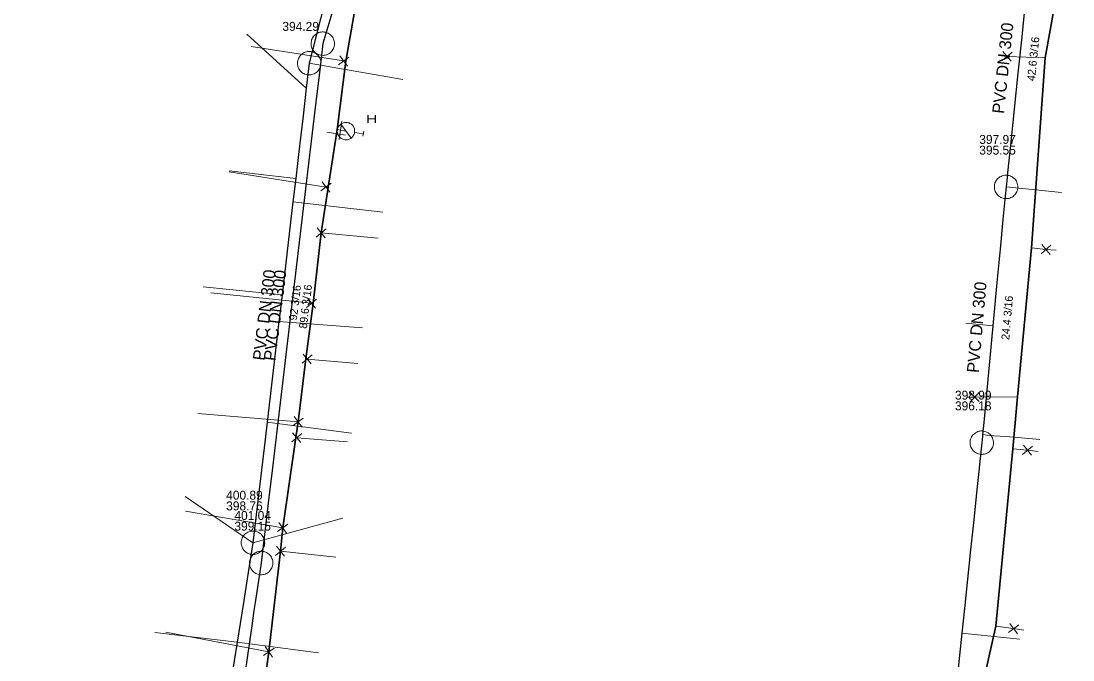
# Model space of a CAD drawing. Extents: x -772952 to -772403, y -1033777 to -1033210.
# Drawn here: x -772837.8 to -772731.9, y -1033431 to -1033366.6 of the extents above; entities that cross this region are included whole.
import ezdxf

# ---------------------------------------------------------------- set-up
doc = ezdxf.new("R2010")
doc.units = 0
doc.header["$LTSCALE"] = 0.36
for name, color, linetype, lineweight in [('15', 7, 'Continuous', 13), ('16', 7, 'Continuous', 35), ('2', 7, 'Continuous', 25), ('20', 7, 'Continuous', 13), ('4', 7, 'Continuous', 13), ('57', 7, 'Continuous', 13), ('59', 7, 'Continuous', 13)]:
    doc.layers.add(name, color=color, linetype=linetype, lineweight=lineweight)
doc.layers.add('3', color=7, linetype='Continuous')
doc.layers.add('6', color=7, linetype='Continuous')

msp = doc.modelspace()

# ---------------------------------------------------------------- linework, layer by layer
at = {"layer": '15'}
for p, q in [((-772738.012, -1033369.776), (-772739.011, -1033370.611)), ((-772738.098, -1033370.687), (-772738.924, -1033369.695)), ((-772804.771, -1033370.263), (-772805.823, -1033371.03)), ((-772804.917, -1033371.166), (-772805.674, -1033370.122)), ((-772805.749, -1033378.554), (-772805.472, -1033376.712)), ((-772805.101, -1033378.119), (-772806.941, -1033377.836)), ((-772806.536, -1033382.968), (-772807.59, -1033383.732)), ((-772806.684, -1033383.871), (-772807.439, -1033382.825)), ((-772808.058, -1033388.377), (-772807.055, -1033387.548)), ((-772807.967, -1033387.467), (-772807.147, -1033388.463)), ((-772735.097, -1033390.054), (-772734.106, -1033389.209)), ((-772735.02, -1033389.142), (-772734.185, -1033390.126)), ((-772808.022, -1033394.638), (-772809.031, -1033395.459)), ((-772808.12, -1033395.547), (-772808.932, -1033394.545)), ((-772809.46, -1033401.071), (-772808.46, -1033400.238)), ((-772809.373, -1033400.16), (-772808.549, -1033401.154)), ((-772741.317, -1033404.029), (-772742.234, -1033404.954)), ((-772741.318, -1033404.944), (-772742.232, -1033404.034)), ((-772810.387, -1033407.365), (-772809.351, -1033406.597)), ((-772809.483, -1033407.502), (-772810.26, -1033406.458)), ((-772810.511, -1033408.996), (-772809.516, -1033408.157)), ((-772810.429, -1033408.085), (-772809.599, -1033409.073)), ((-772736.971, -1033410.255), (-772735.962, -1033409.433)), ((-772736.874, -1033409.345), (-772736.061, -1033410.347)), ((-772810.899, -1033417.277), (-772811.961, -1033418.03)), ((-772811.057, -1033418.178), (-772811.801, -1033417.124)), ((-772812.042, -1033419.512), (-772811.232, -1033420.516)), ((-772812.142, -1033420.421), (-772811.131, -1033419.602)), ((-772738.375, -1033428.185), (-772737.336, -1033427.401)), ((-772738.244, -1033427.279), (-772737.469, -1033428.311)), ((-772812.276, -1033429.761), (-772813.353, -1033430.492)), ((-772812.453, -1033430.659), (-772813.175, -1033429.589))]:
    msp.add_line(p, q, dxfattribs=at)
at = {"layer": '16'}
for points in [[(-772806.021, -1033377.978), (-772805.954, -1033377.548), (-772805.072, -1033370.662), (-772803.861, -1033363.758), (-772800.241, -1033353.386), (-772792.475, -1033337.699)], [(-772752.004, -1033530.359), (-772751.19, -1033518.811), (-772750.826, -1033515.51), (-772749.541, -1033501.15), (-772748.782, -1033492.67), (-772747.697, -1033482.83), (-772745.37, -1033461.714), (-772744.103, -1033448.559), (-772744.068, -1033448.195), (-772743.857, -1033446.285), (-772742.735, -1033441.315), (-772739.627, -1033427.552), (-772737.918, -1033409.688), (-772737.464, -1033404.467), (-772736.037, -1033389.46), (-772734.688, -1033370.337), (-772732.3, -1033357.109), (-772731.88, -1033345.97)], [(-772837.765, -1033512.662), (-772833.548, -1033502.146), (-772829.238, -1033493.795), (-772826.857, -1033488.289), (-772826.66, -1033487.846), (-772820.068, -1033470.473), (-772819.886, -1033469.795), (-772816.921, -1033457.655), (-772813.552, -1033435.519), (-772813.35, -1033434.04), (-772813.183, -1033432.822), (-772812.813, -1033430.125), (-772811.638, -1033420.013), (-772811.429, -1033417.653), (-772810.102, -1033408.565), (-772809.872, -1033406.991), (-772809.089, -1033400.644), (-772808.375, -1033395.068), (-772807.557, -1033387.964), (-772806.853, -1033383.381), (-772806.021, -1033377.978)]]:
    msp.add_lwpolyline(points, dxfattribs=at)
at = {"layer": '2'}
for points in [[(-772735.86, -1033356.94), (-772735.964, -1033357.942), (-772736.014, -1033358.425), (-772736.295, -1033361.116), (-772736.676, -1033364.769), (-772737.037, -1033368.227), (-772737.417, -1033371.875), (-772737.796, -1033375.512), (-772738.174, -1033379.131), (-772738.465, -1033381.925), (-772738.512, -1033382.371), (-772738.612, -1033383.334)], [(-772804.68, -1033359.76), (-772805.372, -1033362.098), (-772805.996, -1033364.204), (-772806.588, -1033366.202), (-772807.39, -1033368.91)], [(-772806.72, -1033362.82), (-772807.267, -1033364.982), (-772808.76, -1033370.88)], [(-772807.39, -1033368.91), (-772807.739, -1033371.853), (-772807.957, -1033373.694), (-772808.221, -1033375.921), (-772809.191, -1033384.102), (-772810.296, -1033393.415), (-772811.17, -1033400.791), (-772812.452, -1033411.601), (-772812.81, -1033414.614), (-772813.59, -1033421.19)], [(-772808.76, -1033370.88), (-772809.054, -1033373.394), (-772809.382, -1033376.191), (-772809.838, -1033380.074), (-772810.121, -1033382.493), (-772810.396, -1033384.832), (-772811.495, -1033394.212), (-772811.721, -1033396.139), (-772811.808, -1033396.879), (-772812.998, -1033407.026), (-772813.298, -1033409.587), (-772814.42, -1033419.15)], [(-772738.612, -1033383.334), (-772738.7, -1033384.261), (-772738.924, -1033386.621), (-772739.207, -1033389.594), (-772739.528, -1033392.97), (-772739.941, -1033397.312), (-772740.866, -1033407.047), (-772740.977, -1033408.213), (-772740.998, -1033408.434), (-772741.06, -1033409.08)], [(-772741.06, -1033409.08), (-772741.253, -1033410.929), (-772741.326, -1033411.63), (-772741.587, -1033414.12), (-772741.871, -1033416.843), (-772742.189, -1033419.878), (-772742.495, -1033422.808), (-772742.806, -1033425.788), (-772743.066, -1033428.271), (-772743.3, -1033430.508), (-772744.701, -1033443.912), (-772744.889, -1033445.705), (-772745.203, -1033448.714), (-772745.553, -1033452.058), (-772745.859, -1033454.983), (-772746.171, -1033457.964), (-772746.344, -1033459.622), (-772746.477, -1033460.894), (-772746.527, -1033461.369), (-772746.66, -1033462.606)], [(-772814.42, -1033419.15), (-772814.998, -1033422.779), (-772815.417, -1033425.405), (-772816.014, -1033429.153), (-772817.813, -1033440.441), (-772819.293, -1033449.728), (-772820.068, -1033454.588), (-772820.4, -1033456.67)], [(-772813.59, -1033421.19), (-772813.756, -1033422.304), (-772813.954, -1033423.632), (-772814.184, -1033425.18), (-772814.339, -1033425.976), (-772814.533, -1033427.52), (-772815.252, -1033432.346), (-772815.998, -1033437.348), (-772816.86, -1033443.13), (-772817.761, -1033449.175), (-772818.006, -1033450.823), (-772818.251, -1033452.464), (-772818.488, -1033454.051), (-772818.61, -1033454.87)]]:
    msp.add_lwpolyline(points, dxfattribs=at)
at = {"layer": '20'}
for p, q in [((-772804.537, -1033378.415), (-772805.578, -1033377.007)), ((-772804.181, -1033377.842), (-772803.307, -1033377.973)), ((-772803.267, -1033377.706), (-772803.347, -1033378.241))]:
    msp.add_line(p, q, dxfattribs=at)
msp.add_lwpolyline([(-772805.187, -1033378.581), (-772805.097, -1033378.59), (-772805.006, -1033378.59), (-772804.913, -1033378.579), (-772804.826, -1033378.56), (-772804.738, -1033378.531), (-772804.654, -1033378.493), (-772804.576, -1033378.446), (-772804.501, -1033378.393), (-772804.435, -1033378.33), (-772804.374, -1033378.262), (-772804.321, -1033378.187), (-772804.274, -1033378.107), (-772804.238, -1033378.024), (-772804.21, -1033377.937), (-772804.193, -1033377.846), (-772804.183, -1033377.755), (-772804.183, -1033377.664), (-772804.194, -1033377.573), (-772804.215, -1033377.483), (-772804.244, -1033377.396), (-772804.283, -1033377.313), (-772804.327, -1033377.234), (-772804.383, -1033377.16), (-772804.444, -1033377.093), (-772804.513, -1033377.032), (-772804.588, -1033376.978), (-772804.667, -1033376.934), (-772804.752, -1033376.897), (-772804.839, -1033376.87), (-772804.929, -1033376.85), (-772805.019, -1033376.843), (-772805.11, -1033376.843), (-772805.203, -1033376.853), (-772805.29, -1033376.873), (-772805.378, -1033376.902), (-772805.462, -1033376.94), (-772805.54, -1033376.987), (-772805.615, -1033377.04), (-772805.681, -1033377.103), (-772805.742, -1033377.171), (-772805.795, -1033377.246), (-772805.842, -1033377.326), (-772805.877, -1033377.41), (-772805.906, -1033377.496), (-772805.923, -1033377.587), (-772805.933, -1033377.678), (-772805.931, -1033377.77), (-772805.922, -1033377.86), (-772805.901, -1033377.95), (-772805.872, -1033378.037), (-772805.833, -1033378.12), (-772805.789, -1033378.199), (-772805.733, -1033378.272), (-772805.672, -1033378.34), (-772805.603, -1033378.401), (-772805.528, -1033378.455), (-772805.449, -1033378.499), (-772805.364, -1033378.536), (-772805.277, -1033378.563), (-772805.189, -1033378.581)], dxfattribs=at)
at = {"layer": '4'}
for points in [[(-772806.21, -1033368.91), (-772806.216, -1033368.791), (-772806.234, -1033368.674), (-772806.263, -1033368.558), (-772806.304, -1033368.447), (-772806.356, -1033368.34), (-772806.419, -1033368.239), (-772806.492, -1033368.144), (-772806.573, -1033368.058), (-772806.663, -1033367.98), (-772806.761, -1033367.911), (-772806.864, -1033367.853), (-772806.973, -1033367.806), (-772807.087, -1033367.769), (-772807.203, -1033367.744), (-772807.321, -1033367.732), (-772807.44, -1033367.731), (-772807.559, -1033367.742), (-772807.675, -1033367.765), (-772807.789, -1033367.799), (-772807.899, -1033367.845), (-772808.004, -1033367.902), (-772808.102, -1033367.969), (-772808.193, -1033368.045), (-772808.276, -1033368.13), (-772808.35, -1033368.224), (-772808.414, -1033368.324), (-772808.468, -1033368.43), (-772808.511, -1033368.541), (-772808.543, -1033368.655), (-772808.562, -1033368.773), (-772808.57, -1033368.892), (-772808.566, -1033369.01), (-772808.55, -1033369.128), (-772808.522, -1033369.244), (-772808.483, -1033369.356), (-772808.432, -1033369.464), (-772808.371, -1033369.566), (-772808.3, -1033369.662), (-772808.22, -1033369.749), (-772808.131, -1033369.829), (-772808.035, -1033369.899), (-772807.932, -1033369.959), (-772807.824, -1033370.008), (-772807.711, -1033370.046), (-772807.595, -1033370.072), (-772807.477, -1033370.087), (-772807.358, -1033370.09), (-772807.24, -1033370.081), (-772807.122, -1033370.06), (-772807.008, -1033370.027), (-772806.898, -1033369.983), (-772806.792, -1033369.928), (-772806.693, -1033369.862), (-772806.6, -1033369.787), (-772806.516, -1033369.703), (-772806.441, -1033369.611), (-772806.375, -1033369.512), (-772806.319, -1033369.407), (-772806.275, -1033369.297), (-772806.241, -1033369.183), (-772806.22, -1033369.066), (-772806.21, -1033368.947)], [(-772807.58, -1033370.88), (-772807.586, -1033370.761), (-772807.604, -1033370.644), (-772807.633, -1033370.528), (-772807.674, -1033370.417), (-772807.726, -1033370.31), (-772807.789, -1033370.209), (-772807.862, -1033370.114), (-772807.943, -1033370.028), (-772808.033, -1033369.95), (-772808.131, -1033369.881), (-772808.234, -1033369.823), (-772808.343, -1033369.776), (-772808.457, -1033369.739), (-772808.573, -1033369.714), (-772808.691, -1033369.702), (-772808.81, -1033369.701), (-772808.929, -1033369.712), (-772809.045, -1033369.735), (-772809.159, -1033369.769), (-772809.269, -1033369.815), (-772809.374, -1033369.872), (-772809.472, -1033369.939), (-772809.563, -1033370.015), (-772809.646, -1033370.1), (-772809.72, -1033370.194), (-772809.784, -1033370.294), (-772809.838, -1033370.4), (-772809.881, -1033370.511), (-772809.913, -1033370.625), (-772809.932, -1033370.743), (-772809.94, -1033370.862), (-772809.936, -1033370.98), (-772809.92, -1033371.098), (-772809.892, -1033371.214), (-772809.853, -1033371.326), (-772809.802, -1033371.434), (-772809.741, -1033371.536), (-772809.67, -1033371.632), (-772809.59, -1033371.719), (-772809.501, -1033371.799), (-772809.405, -1033371.869), (-772809.302, -1033371.929), (-772809.194, -1033371.978), (-772809.081, -1033372.016), (-772808.965, -1033372.042), (-772808.847, -1033372.057), (-772808.728, -1033372.06), (-772808.61, -1033372.051), (-772808.492, -1033372.03), (-772808.378, -1033371.997), (-772808.268, -1033371.953), (-772808.162, -1033371.898), (-772808.063, -1033371.832), (-772807.97, -1033371.757), (-772807.886, -1033371.673), (-772807.811, -1033371.581), (-772807.745, -1033371.482), (-772807.689, -1033371.377), (-772807.645, -1033371.267), (-772807.611, -1033371.153), (-772807.59, -1033371.036), (-772807.58, -1033370.917)], [(-772737.431, -1033383.334), (-772737.438, -1033383.215), (-772737.456, -1033383.098), (-772737.485, -1033382.982), (-772737.526, -1033382.871), (-772737.578, -1033382.764), (-772737.641, -1033382.663), (-772737.713, -1033382.568), (-772737.794, -1033382.482), (-772737.885, -1033382.404), (-772737.983, -1033382.335), (-772738.086, -1033382.277), (-772738.195, -1033382.23), (-772738.309, -1033382.193), (-772738.424, -1033382.168), (-772738.543, -1033382.156), (-772738.662, -1033382.155), (-772738.781, -1033382.166), (-772738.897, -1033382.189), (-772739.011, -1033382.223), (-772739.12, -1033382.269), (-772739.225, -1033382.326), (-772739.324, -1033382.393), (-772739.414, -1033382.469), (-772739.498, -1033382.554), (-772739.571, -1033382.648), (-772739.636, -1033382.748), (-772739.69, -1033382.854), (-772739.733, -1033382.965), (-772739.765, -1033383.079), (-772739.784, -1033383.197), (-772739.792, -1033383.316), (-772739.788, -1033383.434), (-772739.772, -1033383.552), (-772739.744, -1033383.668), (-772739.705, -1033383.78), (-772739.654, -1033383.888), (-772739.593, -1033383.99), (-772739.522, -1033384.086), (-772739.441, -1033384.173), (-772739.353, -1033384.253), (-772739.257, -1033384.323), (-772739.154, -1033384.383), (-772739.046, -1033384.432), (-772738.933, -1033384.47), (-772738.816, -1033384.496), (-772738.699, -1033384.511), (-772738.58, -1033384.514), (-772738.462, -1033384.505), (-772738.343, -1033384.484), (-772738.23, -1033384.451), (-772738.12, -1033384.407), (-772738.014, -1033384.352), (-772737.914, -1033384.286), (-772737.821, -1033384.211), (-772737.738, -1033384.127), (-772737.663, -1033384.035), (-772737.597, -1033383.936), (-772737.541, -1033383.831), (-772737.497, -1033383.721), (-772737.463, -1033383.607), (-772737.441, -1033383.49), (-772737.431, -1033383.371)], [(-772739.88, -1033409.08), (-772739.886, -1033408.961), (-772739.904, -1033408.844), (-772739.933, -1033408.728), (-772739.974, -1033408.617), (-772740.026, -1033408.51), (-772740.089, -1033408.409), (-772740.162, -1033408.314), (-772740.243, -1033408.228), (-772740.333, -1033408.15), (-772740.431, -1033408.081), (-772740.534, -1033408.023), (-772740.643, -1033407.976), (-772740.757, -1033407.939), (-772740.873, -1033407.914), (-772740.991, -1033407.902), (-772741.11, -1033407.901), (-772741.229, -1033407.912), (-772741.345, -1033407.935), (-772741.459, -1033407.969), (-772741.569, -1033408.015), (-772741.674, -1033408.072), (-772741.772, -1033408.139), (-772741.863, -1033408.215), (-772741.946, -1033408.3), (-772742.02, -1033408.394), (-772742.084, -1033408.494), (-772742.138, -1033408.6), (-772742.181, -1033408.711), (-772742.213, -1033408.825), (-772742.232, -1033408.943), (-772742.24, -1033409.062), (-772742.236, -1033409.18), (-772742.22, -1033409.298), (-772742.192, -1033409.414), (-772742.153, -1033409.526), (-772742.102, -1033409.634), (-772742.041, -1033409.736), (-772741.97, -1033409.832), (-772741.89, -1033409.919), (-772741.801, -1033409.999), (-772741.705, -1033410.069), (-772741.602, -1033410.129), (-772741.494, -1033410.178), (-772741.381, -1033410.216), (-772741.265, -1033410.242), (-772741.147, -1033410.257), (-772741.028, -1033410.26), (-772740.91, -1033410.251), (-772740.792, -1033410.23), (-772740.678, -1033410.197), (-772740.568, -1033410.153), (-772740.462, -1033410.098), (-772740.363, -1033410.032), (-772740.27, -1033409.957), (-772740.186, -1033409.873), (-772740.111, -1033409.781), (-772740.045, -1033409.682), (-772739.989, -1033409.577), (-772739.945, -1033409.467), (-772739.911, -1033409.353), (-772739.89, -1033409.236), (-772739.88, -1033409.117)], [(-772813.24, -1033419.15), (-772813.246, -1033419.031), (-772813.264, -1033418.914), (-772813.293, -1033418.798), (-772813.334, -1033418.687), (-772813.386, -1033418.58), (-772813.449, -1033418.479), (-772813.522, -1033418.384), (-772813.603, -1033418.298), (-772813.693, -1033418.22), (-772813.791, -1033418.151), (-772813.894, -1033418.093), (-772814.003, -1033418.046), (-772814.117, -1033418.009), (-772814.233, -1033417.984), (-772814.351, -1033417.972), (-772814.47, -1033417.971), (-772814.589, -1033417.982), (-772814.705, -1033418.005), (-772814.819, -1033418.039), (-772814.929, -1033418.085), (-772815.034, -1033418.142), (-772815.132, -1033418.209), (-772815.223, -1033418.285), (-772815.306, -1033418.37), (-772815.38, -1033418.464), (-772815.444, -1033418.564), (-772815.498, -1033418.67), (-772815.541, -1033418.781), (-772815.573, -1033418.895), (-772815.592, -1033419.013), (-772815.6, -1033419.132), (-772815.596, -1033419.25), (-772815.58, -1033419.368), (-772815.552, -1033419.484), (-772815.513, -1033419.596), (-772815.462, -1033419.704), (-772815.401, -1033419.806), (-772815.33, -1033419.902), (-772815.25, -1033419.989), (-772815.161, -1033420.069), (-772815.065, -1033420.139), (-772814.962, -1033420.199), (-772814.854, -1033420.248), (-772814.741, -1033420.286), (-772814.625, -1033420.312), (-772814.507, -1033420.327), (-772814.388, -1033420.33), (-772814.27, -1033420.321), (-772814.152, -1033420.3), (-772814.038, -1033420.267), (-772813.928, -1033420.223), (-772813.822, -1033420.168), (-772813.723, -1033420.102), (-772813.63, -1033420.027), (-772813.546, -1033419.943), (-772813.471, -1033419.851), (-772813.405, -1033419.752), (-772813.349, -1033419.647), (-772813.305, -1033419.537), (-772813.271, -1033419.423), (-772813.25, -1033419.306), (-772813.24, -1033419.187)], [(-772812.409, -1033421.19), (-772812.416, -1033421.071), (-772812.434, -1033420.954), (-772812.463, -1033420.838), (-772812.504, -1033420.727), (-772812.556, -1033420.62), (-772812.619, -1033420.519), (-772812.691, -1033420.424), (-772812.772, -1033420.338), (-772812.863, -1033420.26), (-772812.961, -1033420.191), (-772813.064, -1033420.133), (-772813.173, -1033420.086), (-772813.287, -1033420.049), (-772813.402, -1033420.024), (-772813.521, -1033420.012), (-772813.64, -1033420.011), (-772813.759, -1033420.022), (-772813.875, -1033420.045), (-772813.989, -1033420.079), (-772814.098, -1033420.125), (-772814.203, -1033420.182), (-772814.302, -1033420.249), (-772814.392, -1033420.325), (-772814.476, -1033420.41), (-772814.549, -1033420.504), (-772814.614, -1033420.604), (-772814.668, -1033420.71), (-772814.711, -1033420.821), (-772814.743, -1033420.935), (-772814.762, -1033421.053), (-772814.77, -1033421.172), (-772814.766, -1033421.29), (-772814.75, -1033421.408), (-772814.722, -1033421.524), (-772814.683, -1033421.636), (-772814.632, -1033421.744), (-772814.571, -1033421.846), (-772814.5, -1033421.942), (-772814.419, -1033422.029), (-772814.331, -1033422.109), (-772814.235, -1033422.179), (-772814.132, -1033422.239), (-772814.024, -1033422.288), (-772813.911, -1033422.326), (-772813.794, -1033422.352), (-772813.677, -1033422.367), (-772813.558, -1033422.37), (-772813.44, -1033422.361), (-772813.321, -1033422.34), (-772813.208, -1033422.307), (-772813.098, -1033422.263), (-772812.992, -1033422.208), (-772812.892, -1033422.142), (-772812.799, -1033422.067), (-772812.716, -1033421.983), (-772812.641, -1033421.891), (-772812.575, -1033421.792), (-772812.519, -1033421.687), (-772812.475, -1033421.577), (-772812.441, -1033421.463), (-772812.419, -1033421.346), (-772812.409, -1033421.227)]]:
    msp.add_lwpolyline(points, close=True, dxfattribs=at)
at = {"layer": '57'}
for p, q in [((-772809.054, -1033373.394), (-772815.03, -1033367.97)), ((-772808.76, -1033370.88), (-772799.332, -1033372.512)), ((-772810.121, -1033382.493), (-772816.81, -1033381.71)), ((-772738.612, -1033383.334), (-772733.04, -1033383.89)), ((-772810.396, -1033384.832), (-772801.35, -1033385.89)), ((-772811.495, -1033394.212), (-772819.44, -1033393.39)), ((-772811.808, -1033396.879), (-772803.39, -1033397.53)), ((-772739.941, -1033397.312), (-772742.68, -1033397.04)), ((-772812.998, -1033407.026), (-772804.49, -1033408.13)), ((-772814.42, -1033419.15), (-772821.23, -1033414.5)), ((-772814.42, -1033419.15), (-772805.38, -1033416.68)), ((-772816.014, -1033429.153), (-772824.29, -1033428.18)), ((-772743.066, -1033428.271), (-772737.24, -1033428.87)), ((-772816.014, -1033429.153), (-772807.81, -1033430.23))]:
    msp.add_line(p, q, dxfattribs=at)
msp.add_lwpolyline([(-772740.977, -1033408.213), (-772740.453, -1033408.373), (-772738.589, -1033408.453), (-772735.22, -1033408.77)], dxfattribs=at)
at = {"layer": '59'}
for p, q in [((-772807.558, -1033387.964), (-772801.822, -1033388.503)), ((-772811.429, -1033417.653), (-772821.21, -1033415.99)), ((-772811.638, -1033420.013), (-772806.065, -1033420.594)), ((-772812.814, -1033430.126), (-772823.176, -1033428.147))]:
    msp.add_line(p, q, dxfattribs=at)
for points in [[(-772805.072, -1033370.662), (-772805.296, -1033370.646), (-772814.603, -1033369.188)], [(-772734.689, -1033370.337), (-772738.511, -1033370.193), (-772739.379, -1033370.116)], [(-772805.955, -1033377.548), (-772805.611, -1033377.634), (-772805.058, -1033377.717)], [(-772806.853, -1033383.382), (-772807.062, -1033383.35), (-772816.828, -1033381.799)], [(-772736.037, -1033389.461), (-772734.603, -1033389.633), (-772733.565, -1033389.715)], [(-772808.376, -1033395.068), (-772808.526, -1033395.048), (-772818.676, -1033394.01)], [(-772809.09, -1033400.645), (-772808.962, -1033400.656), (-772803.848, -1033401.118)], [(-772737.464, -1033404.467), (-772741.775, -1033404.491), (-772742.541, -1033404.495)], [(-772809.872, -1033406.991), (-772809.871, -1033406.982), (-772819.983, -1033406.137)], [(-772810.102, -1033408.564), (-772810.015, -1033408.578), (-772804.897, -1033409.009)], [(-772737.918, -1033409.689), (-772736.468, -1033409.845), (-772735.366, -1033409.957)], [(-772739.628, -1033427.553), (-772737.857, -1033427.794), (-772736.817, -1033427.94)]]:
    msp.add_lwpolyline(points, dxfattribs=at)

# ---------------------------------------------------------------- texts
at = {"layer": '20', "width": 1.45}
msp.add_text('H ', height=0.8, dxfattribs=at).set_placement((-772803.035, -1033376.89))
at = {"layer": '3'}
for s, height, rotation, p in [('PVC DN 300', 1.2, 84, (-772738.824, -1033376.003)), ('42.6 3/16', 0.8, 84, (-772735.719, -1033372.708)), ('PVC DN 300', 1.2, 83, (-772813.253, -1033400.86)), ('PVC DN 300', 1.2, 83, (-772812.161, -1033400.893)), ('PVC DN 300', 1.2, 85, (-772741.372, -1033402.086)), ('92 3/16', 0.8, 83, (-772810.011, -1033396.809)), ('89.6 3/16', 0.8, 83, (-772809.007, -1033397.64)), ('24.4 3/16', 0.8, 85, (-772738.295, -1033398.763))]:
    msp.add_text(s, height=height, rotation=rotation, dxfattribs=at).set_placement(p)
at = {"layer": '6'}
for s, p in [('394.29', (-772811.458, -1033367.624)), ('397.97', (-772741.311, -1033379.002)), ('395.55', (-772741.311, -1033380.079)), ('398.99', (-772743.758, -1033404.748)), ('396.18', (-772743.758, -1033405.825)), ('400.89', (-772817.118, -1033414.818)), ('398.76', (-772817.118, -1033415.895)), ('401.04', (-772816.289, -1033416.858)), ('399.15', (-772816.289, -1033417.935))]:
    msp.add_text(s, height=0.9, dxfattribs=at).set_placement(p)

doc.saveas('drawing.dxf')
